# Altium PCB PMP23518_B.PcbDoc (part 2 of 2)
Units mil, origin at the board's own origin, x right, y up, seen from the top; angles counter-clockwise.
Board outline 2200 x 2200 mil, 2 copper layers (Top Layer, Bottom Layer), stack 62 mil thick; 74 components, 34 nets, 163 pads, 51 vias.
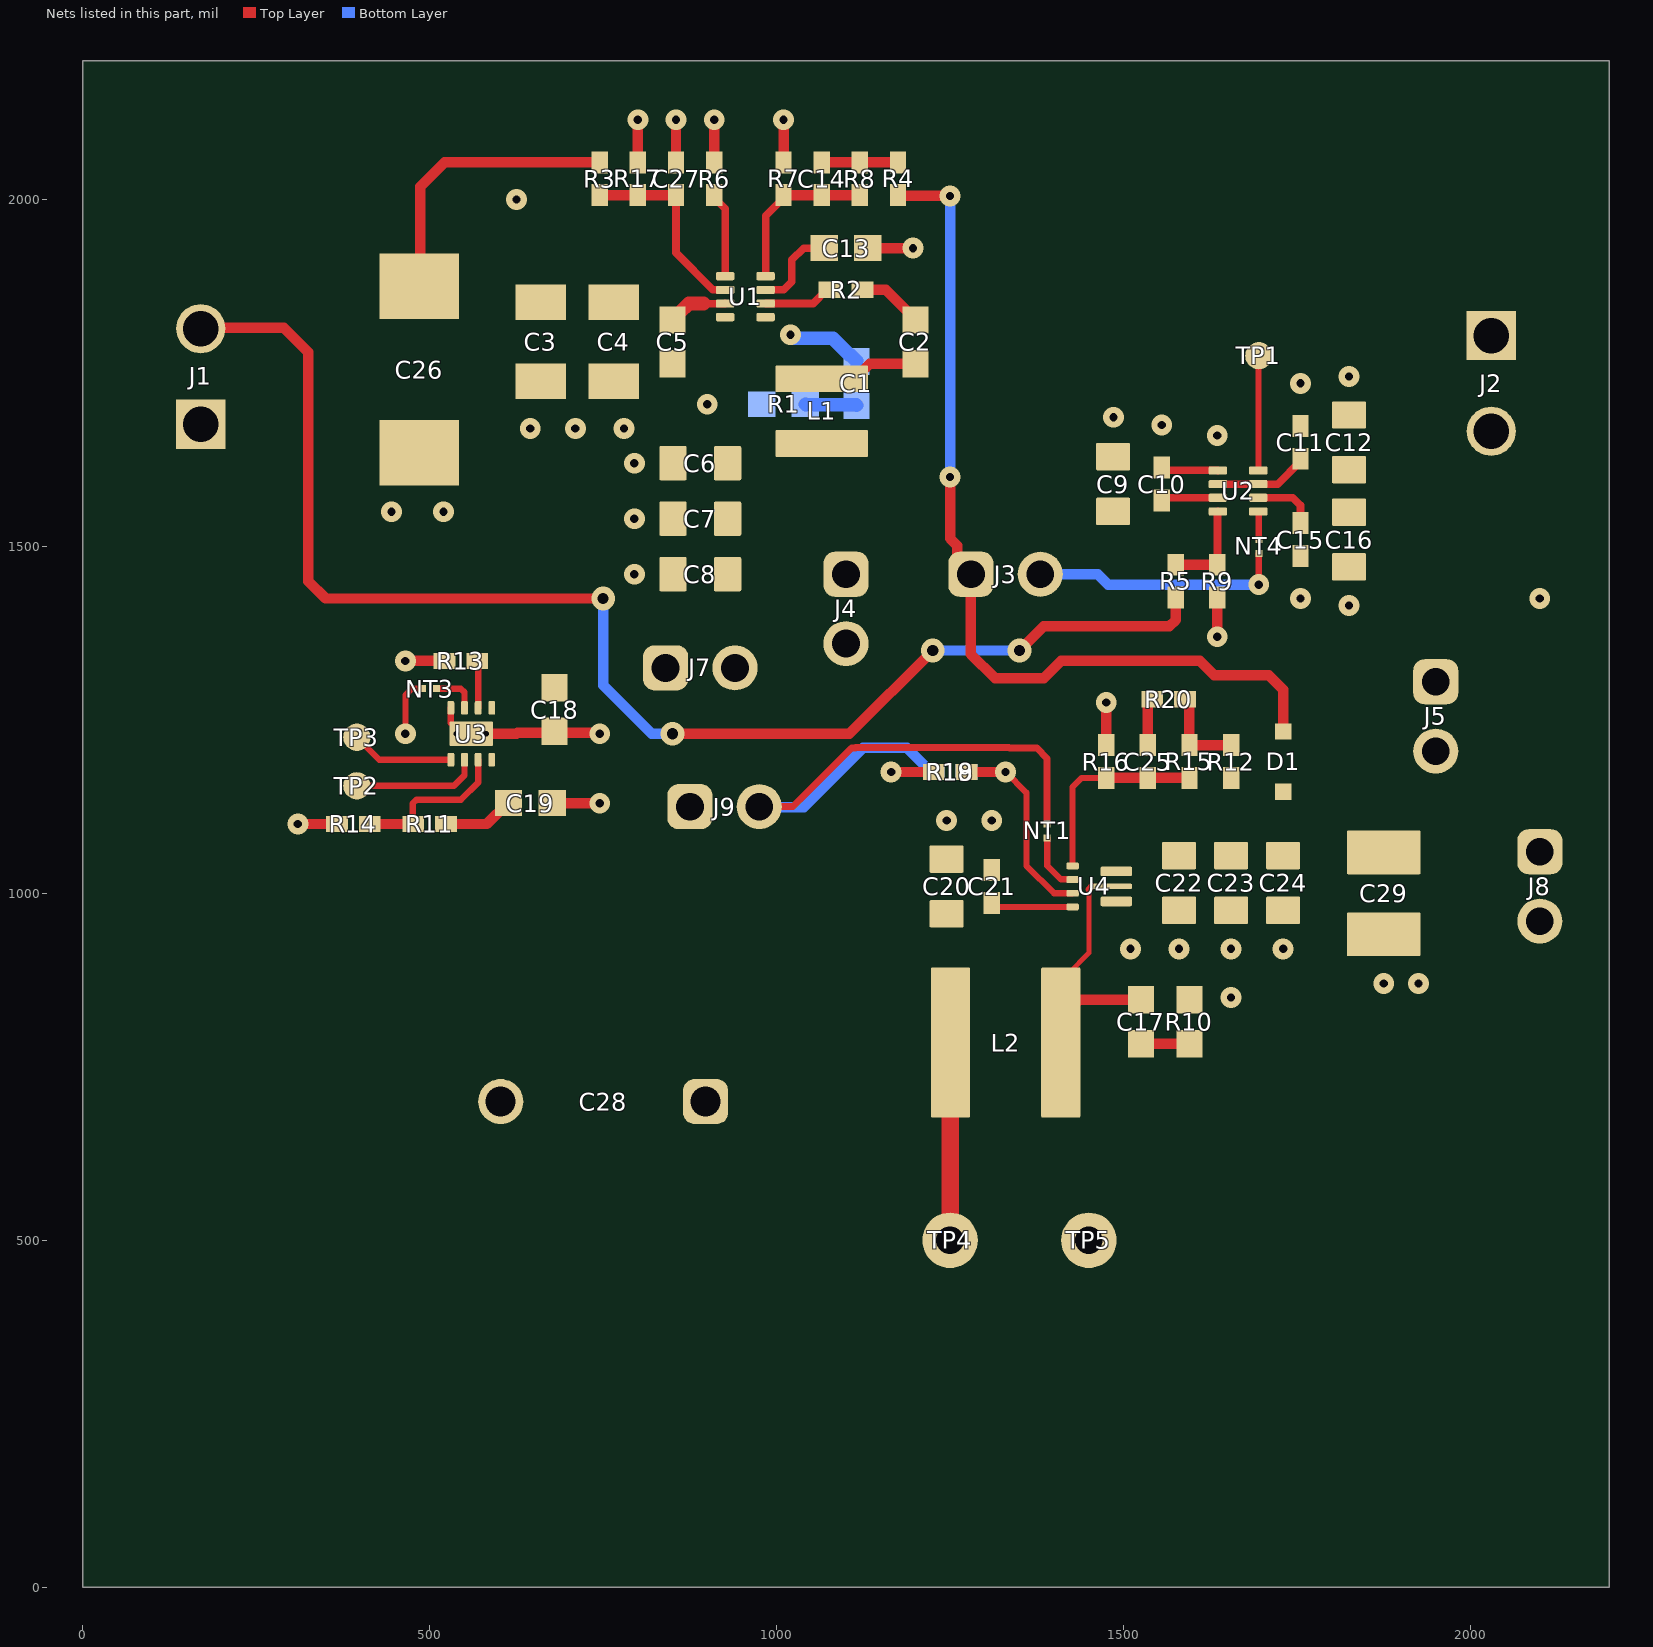
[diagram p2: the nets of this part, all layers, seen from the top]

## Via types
v1: diameter 30, hole 12, Top Layer to Bottom Layer, 45 vias
v2: diameter 34, hole 16, Top Layer to Bottom Layer, 4 vias
v3: diameter 19.68, hole 7.87, Top Layer to Bottom Layer, 2 vias

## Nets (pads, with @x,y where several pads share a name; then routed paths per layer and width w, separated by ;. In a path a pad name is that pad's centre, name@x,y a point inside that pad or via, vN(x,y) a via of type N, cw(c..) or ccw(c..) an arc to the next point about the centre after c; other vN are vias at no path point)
GND: C3.1 C4.1 C5.1 C6.1 C7.1 C8.1 C9.1 C10.2 C11.2 C12.1 C13.1 C15.2 C16.2 C18.1 C19.1 C20.1 C21.2 C22.1 C23.1 C24.1 C26.2 C27.1 C28.2 C29.2 J1.1 J2.1 J4.2 J8.2 NT3.1 R1.2 R6.2 R7.2 R9.2 R10.2 R13.2 R14.2 R16.2 R17.2 R19.1 TP5.1 U1.4 U2.1 U3.4 U3.9 U4.1 | length 1045.1
  Top Layer w9: v1(465,1230) 465,1285.69 474.31,1295 NT3.1@490,1295 ; U3.4@530.47,1267.4 530.47,1245.75 538.35,1237.87 v3(538.35,1230)
  Top Layer w11: C10.2@1555,1613.62 1558.69,1609.93 1635.46,1609.93 U2.1@1635.87,1609.53
  Top Layer w15: v1(310,1100) R14.2@366.38,1100 ; v1(465,1335) R13.2@521.38,1335 ; v3(581.65,1230) 625,1230 626.75,1231.75 678.25,1231.75 C18.1@680,1233.5 681.75,1231.75 743.25,1231.75 v1(745,1230) ; C19.1@676.5,1130 v1(745,1130) ; R17.2@800,2053.62 v1(800,2115) ; C27.1@855,2053.62 v1(855,2115) ; R6.2@910,2053.62 v1(910,2115) ; R7.2@1010,2053.62 v1(1010,2115) ; C13.1@1131.5,1930 v1(1196.65,1930) ; v1(1165,1175) R19.1@1226.38,1175 ; R16.2@1475,1213.62 v1(1475,1275) ; v1(1635,1370) R9.2@1635,1426.38
  other v1: 1655,850 1875,870 1925,870 1510,920 1580,920 1655,920 1730,920 1245,1105 1310,1105 1825,1415 1755,1425 2100,1425 795,1460 795,1540 445,1550 520,1550 795,1620 1635,1660 645,1670 710,1670 780,1670 1555,1675 1485.52,1686.3 900,1705 1755,1735 1825,1745 625,2000
NetC1_1: C1.1 R1.1 | length 74.1
  Bottom Layer w20: R1.1@1041.5,1705 1042.24,1704.25 1114.25,1704.25 C1.1@1115,1703.5
NetC1_2: C1.2 C2.2 L1.1 U1.5 | length 248.5
  Top Layer w15: L1.1@1065,1741.65 1112.64,1741.65 1134.49,1763.5 C2.2@1200,1763.5
  Bottom Layer w20: v1@1025,1800 1081.5,1800 1105.31,1776.18 1106.3,1776.18 1115,1767.48 C1.2@1115,1766.5
  other v1: 1020,1805
NetC2_1: C2.1 R2.2 | length 95
  Top Layer w15: R2.2@1123.62,1870 1157.48,1870 1200,1827.48 C2.1@1200,1826.5
NetC9_2: C9.2 C10.1 J3.2 NT4.2 U2.3 | length 448.6
  Top Layer w9: v1(1695,1445) NT4.2@1695,1490
  Top Layer w11: C10.1@1555,1566.38 1558.78,1570.16 U2.3@1635.87,1570.16
  Bottom Layer w15: J3.2@1380,1460 1462.87,1460 1477.87,1445 v1(1695,1445)
NetC11_1: C11.1 C12.2 J2.2 U2.2 U2.7 | length 136.6
  Top Layer w11: U2.2@1635.87,1589.84 U2.7@1694.13,1589.84 1722.4,1589.84 1755,1622.44 C11.1@1755,1626.38
NetC13_2: C13.2 U1.7 | length 127.6
  Top Layer w11: U1.7@984.13,1869.84 1010.03,1869.84 1022,1881.81 1022,1913.02 1038.98,1930 C13.2@1068.5,1930
NetC14_1: C14.1 R4.1 R8.1 | length 110
  Top Layer w15: C14.1@1065,2053.62 R8.1@1120,2053.62 R4.1@1175,2053.62
NetC14_2: C14.2 R7.1 R8.2 U1.8 | length 237.6
  Top Layer w11: U1.8@984.13,1889.53 984.13,1976.57 1010,2002.44 R7.1@1010,2006.38
  Top Layer w15: R7.1@1010,2006.38 C14.2@1065,2006.38 R8.2@1120,2006.38
NetC15_1: C15.1 C16.1 J5.1 U2.6 | length 91
  Top Layer w11: U2.6@1694.13,1570.16 1744.06,1570.16 1755,1559.21 C15.1@1755,1533.62
NetC17_1: C17.1 R10.1 | length 70
  Top Layer w15: C17.1@1525,783.5 R10.1@1595,783.5
NetC17_2: C17.2 L2.2 U4.2 | length 350
  Top Layer w7: L2.2@1420.16,830.77 1420.16,884.29 1450,914.13 1450,1005.9 ; 1454.1,1010 U4.2@1483.7,1010
  Top Layer w10: 1450,1005.9 1454.1,1010
  Top Layer w15: L2.2@1420.16,815 1420.16,830.77 1435.89,846.5 C17.2@1525,846.5
NetC18_2: C18.2 J7.1 U3.1
NetC19_2: C19.2 J9.1 R11.1 U3.8 | length 102.3
  Top Layer w15: R11.1@523.62,1100 582.52,1100 612.52,1130 C19.2@613.5,1130
NetC20_2: C20.2 C21.1 C28.1 J9.2 L2.1 NT1.1 R18.1 TP4.1 U4.7 | length 1257.2
  Top Layer w9: C21.1@1310,986.38 1315.91,980.47 U4.7@1426.61,980.47
  Top Layer w10: J9.2@975,1125 1023.62,1125 1108.25,1209.63 1113.44,1209.63 1113.81,1210 1335,1210 1335.37,1209.63 1375,1209.63 1390,1194.63 NT1.1@1390,1100
  Top Layer w25: TP4.1@1250,500 1250.24,500.24 1250.24,784.76 L2.1@1250.47,785
  Bottom Layer w15: J9.2@975,1125 975.76,1124.24 1038.98,1124.24 1124.73,1210 1187.44,1210 1222.44,1175 R18.1@1226.38,1175
NetC22_2: C22.2 C23.2 C24.2 C29.1 D1.1 J5.2 J8.1 R12.2 U4.3
NetC25_1: C25.1 R20.1 | length 70.2
  Top Layer w15: C25.1@1535,1213.62 1535,1275.69 1539.31,1280 R20.1@1541.38,1280
NetC25_2: C25.2 R15.2 R16.1 U4.4 | length 287.6
  Top Layer w9: U4.4@1426.61,1039.53 1426.61,1153.42 1439.58,1166.38 R16.1@1475,1166.38
  Top Layer w15: R16.1@1475,1166.38 C25.2@1535,1166.38 R15.2@1595,1166.38
NetC27_2: C27.2 R3.2 R17.1 U1.2 | length 286
  Top Layer w11: C27.2@855,2006.38 855,1923.53 908.28,1870.25 925.46,1870.25 U1.2@925.87,1869.84
  Top Layer w15: R3.2@745,2006.38 R17.1@800,2006.38 C27.2@855,2006.38
NetNT1_2: NT1.2 U4.5 | length 85
  Top Layer w9: NT1.2@1390,1080 1390,1040 1409.74,1020.26 1426.19,1020.26 U4.5@1426.61,1019.84
NetNT3_2: NT3.2 U3.3 | length 64.7
  Top Layer w9: NT3.2@510,1295 544.89,1295 550.16,1289.73 U3.3@550.16,1267.4
NetNT4_1: NT4.1 U2.5 | length 40.8
  Top Layer w9: U2.5@1694.13,1550.47 1695,1549.61 NT4.1@1695,1510
NetR2_1: R2.1 U1.6 | length 100.5
  Top Layer w11: U1.6@984.13,1850.16 1052.6,1850.16 1072.44,1870 R2.1@1076.38,1870
NetR5_2: R5.2 R9.1 U2.4 | length 137.2
  Top Layer w11: R9.1@1635,1473.62 1635.43,1474.05 1635.43,1550.07 U2.4@1635.84,1550.47
  Top Layer w15: R5.2@1575,1473.62 R9.1@1635,1473.62
NetR6_1: R6.1 U1.1 | length 123.4
  Top Layer w11: R6.1@910,2006.38 910,2002.44 925.87,1986.57 U1.1@925.87,1889.53
NetR11_2: R11.2 R14.1 U3.7 | length 230.8
  Top Layer w9: R11.2@475.69,1100.69 475.69,1129.73 480.96,1135 545,1135 569.84,1159.84 U3.7@569.84,1192.6
  Top Layer w15: R14.1@413.62,1100 475,1100 R11.2@475.69,1100.69
NetR12_1: R12.1 R15.1 R20.2 | length 130.2
  Top Layer w15: R20.2@1588.62,1280 1590.69,1280 1595,1275.69 R15.1@1595,1213.62 R12.1@1655,1213.62
NetR13_1: R13.1 U3.2 | length 68.1
  Top Layer w9: R13.1@568.62,1335 569.84,1333.78 U3.2@569.84,1267.4
NetR18_2: R18.2 R19.2 U4.6 | length 343.3
  Top Layer w9: v1(1330,1175) 1360,1145 1360,1040 1399.84,1000.16 U4.6@1426.61,1000.16
  Top Layer w15: R19.2@1273.62,1175 v1(1330,1175)
  Bottom Layer w15: R18.2@1273.62,1175 v1(1330,1175)
NetTP1_1: TP1.1 U2.8 | length 165.8
  Top Layer w9: U2.8@1694.13,1609.53 1694.57,1609.96 1694.57,1774.57 TP1.1@1695,1775
NetTP2_1: TP2.1 U3.6 | length 183.9
  Top Layer w9: TP2.1@395,1155 535,1155 550.16,1170.16 U3.6@550.16,1192.6
NetTP3_1: TP3.1 U3.5 | length 148.9
  Top Layer w9: TP3.1@395,1225 427.4,1192.6 U3.5@530.47,1192.6
VBUCK: C6.2 C7.2 C8.2 D1.2 J3.1 J4.1 J7.2 L1.2 R4.2 | length 1300.3
  Top Layer w15: R4.2@1175,2006.38 1175.69,2005.69 1249.31,2005.69 v1(1250,2005) ; v1(1250,1600) 1250,1511.46 1260.42,1501.04 1260.42,1479.58 J3.1@1280,1460 1280,1345 1315,1310 1385,1310 1410,1335 1610,1335 1630.58,1314.42 1709.13,1314.42 1730,1293.55 D1.2@1730,1233.31
  Bottom Layer w15: v1(1250,1600) v1(1250,2005)
VIN: C3.2 C4.2 C5.2 C26.1 J1.2 R3.1 R5.1 U1.3 | length 2517.5
  Top Layer w11: 895,1850 925.71,1850 U1.3@925.87,1850.16
  Top Layer w15: J1.2@170,1815 290,1815 325,1780 325,1450 350,1425 v2(750,1425) ; C26.1@485,1875.08 486.22,1876.3 486.22,2018.19 521.65,2053.62 R3.1@745,2053.62 ; v2(850,1230) 1105,1230 v2(1225,1350) ; v2(1350,1350) 1385.2,1385.2 1566.21,1385.2 1575,1393.98 R5.1@1575,1426.38
  Top Layer w20: C5.2@850,1826.5 850,1827.48 858.7,1836.18 859.69,1836.18 873.5,1850 895,1850
  Bottom Layer w15: v2(750,1425) 750,1300 820,1230 v2(850,1230) ; v2(1225,1350) v2(1350,1350)

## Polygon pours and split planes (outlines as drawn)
GND on Top Layer "TOP_LAYER_GND_P011" (solid, remove dead copper, pour order 11): 50,2150 50,50 2150,50 2150,2150
NetC18_2 on Top Layer "TOP_LAYER_NETC18_2_P010" (solid, remove dead copper, pour order 10): 895,1275 655,1275 640,1260 585,1260 585,1280 685,1375 895,1375
NetC19_2 on Top Layer "TOP_LAYER_NETC19_2_P009" (solid, remove dead copper, pour order 9): 555,950 910,950 910,1175 800,1175 800,1050 635,1050 635,1200 585,1200 585,1160 555,1130
NetC22_2 on Top Layer "TOP_LAYER_NETC22_2_P008" (solid, remove dead copper, pour order 8): 2150,1025 2150,1240 1800,1240 1800,1180 1640,1180 1640,1100 1465,1100 1465,1025
NetC20_2 on Top Layer "TOP_LAYER_NETC20_2_P007" (solid, remove dead copper, pour order 7): 800,900 940,900 940,1175 1075,1175 1075,1000 1190,1000 1370,1000 1385,985 1400,985 1400,970 1350,970 1350,600 800,600
NetC17_2 on Top Layer "TOP_LAYER_NETC17_2_P006" (solid, remove dead copper, pour order 6): 1445,965 1430,950 1375,950 1375,650 1455,650 1455,1015 1445,1015
NetC11_1 on Top Layer "TOP_LAYER_NETC11_1_P005" (solid, remove dead copper, pour order 5): 1730,1590 2150,1590 2150,1730 1900,1730 1900,1640 1730,1640
NetC15_1 on Top Layer "TOP_LAYER_NETC15_1_P004" (solid, remove dead copper, pour order 4): 1900,1265 1900,1520 1730,1520 1730,1575 2000,1575 2000,1265
NetC9_2 on Top Layer "TOP_LAYER_NETC9_2_P003" (solid, remove dead copper, pour order 3): 1340,1420 1340,1580 1605,1580 1605,1540 1525,1540 1525,1420
VBUCK on Top Layer "TOP_LAYER_VBUCK_P002" (solid, remove dead copper, pour order 2): 905,1275 1000,1275 1000,1420 1315,1420 1315,1550 1160,1550 1160,1680 905,1680
NetC1_2 on Top Layer "TOP_LAYER_NETC1_2_P001" (solid, remove dead copper, pour order 1): 975,1835 975,1700 1160,1700 1160,1800 1050,1800 1015,1835
VIN on Top Layer "TOP_LAYER_VIN_P000" (solid, remove dead copper, pour order 0): 50,1760 550,1760 595,1805 885,1805 885,1860 845,1860 755,1950 50,1950
GND on Bottom Layer "BOTTOM_LAYER_GND_P012" (solid, remove dead copper, pour order 12): 50,2150 2150,2150 2150,50 50,50

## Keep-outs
Keep-Out Layer:
  text ".Layer_Name" at 577,-858.49 h60

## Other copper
Top Layer:
  text ".Layer_Name" at 577,-858.49 h60
Bottom Layer:
  text ".Layer_Name" at 577,-858.49 h60

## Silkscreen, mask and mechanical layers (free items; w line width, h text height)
Top Overlay:
  text "GND" at 1981,1936 h40
  text "VIN" at 71,1919.02 h40
  text "GND" at 71,1516 h40
  text "VOUT" at 1961,1504.19 h40
  text "'.PRJ_Number'.PCB_Rev" at 1565.5,230 h108.27
  text ".Layer_Name" at 577,-858.49 h60
Bottom Overlay:
  text ".Layer_Name" at 577,-858.49 h60
Top Paste:
  text ".Layer_Name" at 577,-858.49 h60
Bottom Paste:
  text ".Layer_Name" at 577,-858.49 h60
Top Solder:
  text ".Layer_Name" at 577,-858.49 h60
  text ".Layer_Name" at 577,-858.49 h60
Bottom Solder:
  text ".Layer_Name" at 577,-858.49 h60
Drill Guide:
  text ".Layer_Name" at 577,-858.49 h60
M1 Board Outline:
  the board outline again, w10
  text ".Layer_Name" at 577,-858.49 h60
M2 Board Dimensions:
  rectangle: 0,-275 125,-150
  rectangle: 125,-400 500,-275
  lines w7: 0,-275 1000,-275 ; 125,-400 125,-150 ; 250,-400 250,-150 ; 500,-400 500,-150 ; 750,-400 750,-150 ; 0,-400 1000,-400 1000,-150 0,-150 0,-400
  text ".Layer_Name" at 577,-858.49 h60
M3 3D STEP Top:
  text ".Layer_Name" at 577,-858.49 h60
M4 3D STEP Bottom:
  text ".Layer_Name" at 577,-858.49 h60
M5 Assembly Top:
  lines w10: -292,-930.17 6308,-930.17 ; -292,-726.83 6310,-726.83 ; -292,-523.5 -292,-1133.5 3713,-1133.5 6310,-1133.5 6310,-523.5 -291.5,-523.5 -291.5,-1133.5 1284,-1133.5 ; 2173,-1133.5 2173,-523.5 ; 3440,-726.83 3440,-523.5 ; 4280,-726.83 4280,-523.5 ; 4902,-1140 4902,-937.17
  text "COMPONENTS MARKED 'DNP' SHOULD NOT BE POPULATED." at 1153.5,-318.5 h60
  text "ASSEMBLY VARIANT:" at 1153,-434 h60
  text ".VariantName" at 2189,-434 h60
  text "PCB VIEWED FROM TOP SIDE" at -228.5,-655.67 h60
  text "BOARD #:" at 2248,-655.67 h60
  text ".PRJ_Number" at 2793.5,-655.67 h60
  text "REV:" at 3638,-655.67 h60
  text ".PCB_Rev" at 3929.5,-655.67 h60
  text "SVN REV:" at 4476,-655.67 h60
  text ".VersionControl_RevNumber" at 4982,-655.67 h60
  text "TID #:" at 2248,-859 h60
  text ".TID" at 2793.5,-859 h60
  text "PLOT NAME =" at -228.5,-1064.34 h60
  text ".plot_File_Name" at 577,-1064.34 h60
  text "GENERATED    :" at 2250,-1064.34 h60
  text ".Print_Date" at 3119.5,-1064.34 h60
  text ".Print_Time" at 3848.5,-1064.34 h60
  text "TEXAS INSTRUMENTS" at 5113,-1064.34 h60
M6 Assembly Bottom:
  lines w10: -292.5,-727.33 6309.5,-727.33 ; -290.5,-930.67 6309.5,-930.67 ; 1115.5,-1140.5 1115.5,-937.67 ; 1737.5,-727.33 1737.5,-524 ; 2577.5,-727.33 2577.5,-524 ; 3844.5,-1134 3844.5,-524 ; 4733.5,-1134 6309,-1134 6309,-524 -292.5,-524 -292.5,-1134 2304.5,-1134 6309.5,-1134 6309.5,-524
  text "COMPONENTS MARKED 'DNP' SHOULD NOT BE POPULATED." at 6102,-318 h60
  text ".VariantName" at 5058,-434 h60
  text "ASSEMBLY VARIANT:" at 6097,-434 h60
  text ".VersionControl_RevNumber" at 1035.5,-656.17 h60
  text "SVN REV:" at 1541.5,-656.17 h60
  text ".PCB_Rev" at 2088,-656.17 h60
  text "REV:" at 2379.5,-656.17 h60
  text ".PRJ_Number" at 3224,-656.17 h60
  text "BOARD #:" at 3769.5,-656.17 h60
  text "PCB VIEWED FROM BOTTOM SIDE" at 6246,-656.17 h60
  text ".TID" at 3224,-859.5 h60
  text "TID #:" at 3769.5,-859.5 h60
  text "TEXAS INSTRUMENTS" at 904.5,-1064.84 h60
  text ".Print_Time" at 2169,-1064.84 h60
  text ".Print_Date" at 2898,-1064.84 h60
  text "GENERATED    :" at 3767.5,-1064.84 h60
  text ".plot_File_Name" at 5440.5,-1064.84 h60
  text "PLOT NAME =" at 6246,-1064.84 h60
M9 Title Sheet:
  drawing of 57 lines, arcs and shapes, not listed
  text "1" at 739.84,8036.5 h70
  text "2" at 3235.5,8036.5 h70
  text "3" at 5724.84,8036.5 h70
  text "4" at 8231.51,8036.5 h70
  text "5" at 10730.5,8036.5 h70
  text "6" at 13235.5,8036.5 h70
  text "A" at -416.5,6893.5 h70
  text "A" at 14383.5,6893.5 h70
  text "B" at -416.5,4513.5 h70
  text "B" at 14383.5,4513.5 h70
  text "C" at -416.5,2138.5 h70
  text "C" at 14383.5,2138.5 h70
  text "PROJECT TITLE:" at 11343.5,277.5 h45
  text ".PRJ_Title" at 11393.5,144.17 h70
  text "DESIGNED FOR:" at 11343.5,-23.5 h45
  text ".PRJ_Customer" at 11393.5,-163.5 h70
  text "D" at -416.5,-231.5 h70
  text "D" at 14383.5,-231.5 h70
  text "FILE NAME:" at 11343.5,-323.5 h45
  text ".PCB_File_Name_No_Path" at 11393.5,-443.5 h70
  text "Texas Instruments (TI) and/or its licensors do not warrant the accuracy or completeness of this specification" at 6374,-605.34 h45
  text "ENGINEER:" at 11343.5,-613.5 h45
  text "LAYOUT BY:" at 12848.5,-613.5 h45
  text "or any information contained therein. TI and/or its licensors do not warrant that this design will meet" at 6329.01,-718 h45
  text ".PRJ_Engineer" at 11393.5,-768.49 h70
  text ".PCB_Layout" at 12899,-768.49 h70
  text "the specifications, will be suitable for your application or fit for any particular purpose, or will operate in" at 6329.01,-830.67 h45
  text ".Layer_Name" at 577,-858.49 h60
  text "ALTIUM DESIGNER VERSION:" at 12848.5,-923.5 h45
  text "an implementation. TI and/or its licensors do not warrant that the design is production worthy. You should" at 6329.01,-943.33 h45
  text "completely validate and test your design implementation to confirm the system functionality for your application." at 6374,-1056 h45
  text ".print_Scale" at 11393.5,-1056.83 h70
  text ".Application_BuildNumber" at 12899,-1056.83 h70
  text "1" at 739.84,-1263.5 h70
  text "2" at 3235.5,-1263.5 h70
  text "3" at 5724.84,-1263.5 h70
  text "4" at 8231.51,-1263.5 h70
  text "5" at 10730.5,-1263.5 h70
  text "6" at 13235.5,-1263.5 h70
M10 Fab Notes:
  drawing of 189 lines, arcs and shapes, not listed
  text "DESIGN INFORMATION" at 12382.02,6356.17 h60
  text "MIN. TRACK WIDTH:" at 11737.46,6224.05 h60
  text "8" at 12833.7,6224.05 h60
  text "MIL" at 12988.46,6224.05 h60
  text "7.874" at 12667.32,6102.36 h60
  text "MIN. CLEARANCE:" at 11737.46,6099.92 h60
  text "MIL" at 12988.46,6099.92 h60
  text "MIN. VIA PAD SIZE:" at 11737.46,5975.8 h60
  text "24" at 12803.71,5975.8 h60
  text "MIL" at 12988.46,5975.8 h60
  text "0.05mm (2MIL)" at 12432.46,5845.9 h60
  text "MINIMUM ANNULAR RING" at 11408.23,5837.67 h60
  text "EXTERNAL" at 13140.46,5837.67 h60
  text "PER" at 11608.23,5727.55 h60
  text "IPC-D-275 CLASS 2 LEVEL C" at 11828.23,5727.54 h60
  text "MIL, HOLES" at 13316.46,5627.07 h60
  text "+/-" at 12924,5618.48 h60
  text "+/-" at 13778,5618.48 h60
  text "REGISTRATION TOLERANCES:" at 11408.23,5617.42 h60
  text "METAL" at 12608,5617.42 h60
  text "5" at 13184.2,5617.42 h60
  text "3" at 14017.2,5617.42 h60
  text "MIL" at 14133.46,5617.42 h60
  text "HOLE SIZE TOLERANCE (UNLESS OTHERWISE SPECIFIED):" at 11408.23,5519.1 h60
  text "+/-" at 13778,5516.23 h60
  text "3" at 14017.2,5515.17 h60
  text "MIL" at 14133.46,5515.17 h60
  text "MATERIAL:" at 11333.46,5377.52 h60
  text "FR-4 High Tg" at 12319.9,5249 h60
  text "X" at 12175.46,5241.01 h60
  text "FR-4" at 11754.46,5236.49 h60
  text "OTHER" at 13242.46,5236.49 h60
  text "62 MIL (1.6mm) +/-10%" at 12074.56,5093.46 h60
  text "X" at 11954.46,5091.01 h60
  text "THICKNESS:" at 11408.23,5085.24 h60
  text "OTHER" at 13359.46,5085.24 h60
  text "TOLERANCE:" at 11408.23,4946.92 h60
  text "X" at 12256.46,4946.92 h60
  text "ANSI IPC-6012 TYPE 3 CLASS 2" at 12434.48,4946.92 h60
  text "OTHER +/-" at 12434.46,4802.73 h60
  text "BOW & TWIST:" at 11408.23,4657.54 h60
  text "X" at 12256.46,4657.54 h60
  text "ANSI IPC-6012 TYPE 3 CLASS 2" at 12434.48,4657.54 h60
  text "OTHER +/-" at 12434.46,4510.85 h60
  text "DRILLING:" at 11333.46,4380.23 h60
  text "NC_DRILL FILES" at 13094.46,4275.04 h60
  text "REFERENCE:" at 11408.23,4271.1 h60
  text "X" at 12065.46,4271.01 h60
  text "AS SHOWN" at 12243.46,4271.1 h60
  text "X" at 12966.46,4271.1 h60
  text "OTHER" at 13392.46,4128.85 h60
  text "PTH COPPER THICKNESS:" at 11407.91,4125.32 h60
  text "X" at 12547.14,4125.32 h60
  text "20-30 um" at 12675.14,4125.32 h60
  text "BOARD FINISH:" at 11333.46,3977.73 h60
  text "SILKSCREEN:" at 11488.68,3867.6 h60
  text "X" at 12446.46,3867.6 h60
  text "TOP" at 12563.46,3867.6 h60
  text "X" at 12956.46,3867.6 h60
  text "BOTTOM" at 13074.46,3867.6 h60
  text "SILKSCREEN COLOR:" at 11488.68,3712.41 h60
  text "X" at 12445.46,3712.41 h60
  text "WHITE" at 12563.46,3712.41 h60
  text "OTHER" at 13074.46,3712.41 h60
  text "X" at 12576.46,3568.96 h60
  text "GREEN" at 12694.46,3568.96 h60
  text "OTHER" at 13312.46,3568.96 h60
  text "SOLDER RESIST COLOR:" at 11488.68,3562.1 h60
  text "X" at 12576.46,3414.71 h60
  text "MATTE" at 12694.46,3414.71 h60
  text "SEMI-GLOSS" at 13312,3414.07 h60
  text "IMMERSION GOLD (ENIG)" at 12394.46,3241.94 h60
  text "ENEPIG" at 13732,3234.72 h60
  text "SURFACE FINISH:" at 11333.46,3233.72 h60
  text "X" at 12216.46,3233.72 h60
  text "IMM. TIN/SILVER OR EQUIV" at 11663,3096.4 h60
  text "OTHER" at 13094.46,3092.47 h60
  text "ARRAY/PANEL:" at 11333.46,2937.09 h60
  text "CUT AND TRIM PER M1 BOARD OUTLINE" at 12394.46,2928.87 h60
  text "N.C. ROUTE" at 12394.46,2792.9 h60
  text "X" at 13082.46,2792.9 h60
  text "V. SCORE" at 13260.46,2792.9 h60
  text "CERTIFICATION:" at 11333.46,2663.77 h60
  text "MATERIALS AND WORKMANSHIP FOR ALL PCBS" at 12058.46,2663.77 h60
  text "TO MEET OR EXCEED THE REQUIREMENTS OF:" at 12058.46,2569.71 h60
  text "X" at 11695.97,2441.08 h60
  text "ANSI IPC-A-600F CLASS ->" at 11823.96,2441.08 h60
  text "X" at 13471.97,2441.08 h60
  text "2" at 13581.96,2441.08 h60
  text "1" at 13266.96,2439.58 h60
  text "3" at 13935.96,2439.58 h60
  text "X" at 12507.97,2293.39 h60
  text "RoHS" at 12635.96,2293.39 h60
  text "OTHER" at 13280.36,2293.39 h60
  text "PER ORDER" at 13677.42,2293.39 h60
  text "ALL BOARDS MUST MEET OR EXCEED UL94-V0 REQUIREMENTS." at 11361,2139.57 h60
  text "PCB MUST BEAR THE UL94V-0 UL REGISTERED MATERIAL ID NUMBER" at 11361,2023.5 h60
  text "ADDITIONAL REQUIREMENTS:" at 11333.46,1854.08 h60
  text "MICROSECTION:" at 11408.23,1746.95 h60
  text "YES" at 12313.96,1746.95 h60
  text "REQUIRED" at 13175.46,1602.62 h60
  text "BARE BOARD ELEC. TEST:" at 11408.23,1599.76 h60
  text "NONE" at 12713.96,1599.76 h60
  text "X" at 13057.46,1599.76 h60
  text "PER ORDER" at 13767.46,1599.76 h60
  text "XX MIL VIAS REQUIRE NON-CONDUCTIVE FILL AND PLANARIZE" at 11576.38,1394.82 h59
  text "XX MIL VIAS REQUIRE CONDUCTIVE FILL AND PLANARIZE" at 11584.38,1290.84 h60
  text "OUTER XX MIL TRACES REQUIRE 50 OHM SINGLE-ENDED IMPEDANCE" at 11583.39,1127.46 h58
  text "LAYER 2 & 3 (INNER LAYERS) XX MIL WIDE, XX MIL SPACE / TRACES REQUIRE 100 OHM DIFFERENTIAL IMPEDANCE" at 11575.39,891.74 h60
  text ".Layer_Name" at 577,-858.49 h60
M11 Gerber Information:
  lines w10: -292,-930.17 6308,-930.17 ; -292,-726.83 6310,-726.83 ; -292,-523.5 -292,-1133.5 3713,-1133.5 6310,-1133.5 6310,-523.5 -291.5,-523.5 -291.5,-1133.5 1284,-1133.5 ; 2173,-1133.5 2173,-523.5 ; 3440,-726.83 3440,-523.5 ; 4280,-726.83 4280,-523.5 ; 4902,-1140 4902,-937.17
  text "ALL ARTWORK VIEWED FROM TOP SIDE" at -228.5,-655.67 h60
  text "BOARD #:" at 2248,-655.67 h60
  text ".PRJ_Number" at 2793.5,-655.67 h60
  text "REV:" at 3638,-655.67 h60
  text ".PCB_Rev" at 3929.5,-655.67 h60
  text "SVN REV:" at 4476,-655.67 h60
  text ".VersionControl_RevNumber" at 4982,-655.67 h60
  text "LAYER NAME =" at -228.5,-858.49 h60
  text "TID #:" at 2248,-859 h60
  text ".TID" at 2793.5,-859 h60
  text "PLOT NAME =" at -228.5,-1064.34 h60
  text ".plot_File_Name" at 577,-1064.34 h60
  text "GENERATED    :" at 2250,-1064.34 h60
  text ".Print_Date" at 3119.5,-1064.34 h60
  text ".Print_Time" at 3848.5,-1064.34 h60
  text "TEXAS INSTRUMENTS" at 5113,-1064.34 h60
M12 Stackup:
  drawing of 191 lines, arcs and shapes, not listed
  text "Layer" at 9821.59,7874.94 h60
  text "Name" at 10231.51,7874.94 h60
  text "Material" at 11161.25,7874.94 h60
  text "Thickness" at 12021.02,7874.94 h60
  text "Constant" at 12670.85,7874.94 h60
  text "Board Layer Stack" at 13240.71,7874.94 h60
  text "Top Overlay" at 10231.51,7754.94 h60
  text "Top Solder" at 10231.51,7634.94 h60
  text "Solder Resist" at 11161.25,7634.94 h60
  text "0.40mil" at 12021.02,7634.94 h60
  text "3.5" at 12670.85,7634.94 h60
  text "1" at 9821.59,7514.94 h60
  text "Top Layer" at 10231.51,7514.94 h60
  text "1.40mil" at 12021.02,7514.94 h60
  text "Dielectric1" at 10231.51,7394.94 h60
  text "FR-4 High Tg" at 11161.25,7394.94 h60
  text "59.20mil" at 12021.02,7394.94 h60
  text "4.8" at 12670.85,7394.94 h60
  text "2" at 9821.59,7274.94 h60
  text "Bottom Layer" at 10231.51,7274.94 h60
  text "1.40mil" at 12021.02,7274.94 h60
  text "Bottom Solder" at 10231.51,7154.94 h60
  text "Solder Resist" at 11161.25,7154.94 h60
  text "0.40mil" at 12021.02,7154.94 h60
  text "3.5" at 12670.85,7154.94 h60
  text "Bottom Overlay" at 10231.51,7034.94 h60
  text ".Layer_Name" at 577,-858.49 h60
M13 Component Bodies Top:
  text ".Layer_Name" at 577,-858.49 h60
M14 Component Bodies Bottom:
  text ".Layer_Name" at 577,-858.49 h60
M15 Courtyards Top:
  text ".Layer_Name" at 577,-858.49 h60
M16 Courtyards Bottom:
  text ".Layer_Name" at 577,-858.49 h60
Drill Drawing:
  lines w10: 2630.98,167.23 2630.98,181.02 2644.76,194.8 2630.98,208.58 2630.98,222.36 2644.76,222.36 2658.54,208.58 2672.32,222.36 2686.1,222.36 2686.1,208.58 2672.32,194.8 2686.1,181.02 2686.1,167.23 2672.32,167.23 2658.54,181.02 2644.76,167.23 2630.98,167.23 ; 2630.98,346.38 2686.1,346.38 2658.54,291.26 2630.98,346.38 ; 2630.98,415.29 2686.1,415.29 2686.1,470.41 2630.98,470.41 2630.98,415.29 ; 2630.98,553.1 2644.76,553.1 2644.76,539.31 2672.32,539.31 2672.32,553.1 2686.1,553.1 2686.1,580.66 2672.32,580.66 2672.32,594.44 2644.76,594.44 2644.76,580.66 2630.98,580.66 2630.98,553.1 ; 2630.98,663.34 2658.54,677.12 2686.1,663.34 2672.32,690.9 2686.1,718.46 2658.54,704.68 2630.98,718.46 2644.76,690.9 2630.98,663.34 ; 2630.98,801.15 2644.76,801.15 2658.54,787.37 2672.32,801.15 2686.1,801.15 2672.32,814.93 2686.1,828.71 2672.32,828.71 2658.54,842.49 2644.76,828.71 2630.98,828.71 2644.76,814.93 2630.98,801.15
  lines w12: 2581,130.03 5672.83,130.03 ; 2581,874.19 5672.83,874.19 ; 2918.36,6 2918.36,998.21 ; 3189.17,6 3189.17,998.21 ; 3750.94,6 3750.94,998.21 ; 4009.74,6 4009.74,998.21 ; 4384.49,6 4384.49,998.21 ; 5107.03,6 5107.03,998.21 ; 2581,6 5672.83,6 5672.83,998.21 2581,998.21 2581,6
  text "Symbol" at 2655.42,911.39 h72
  text "Count" at 2955.57,911.39 h72
  text "Hole Size" at 3226.38,911.39 h72
  text "Plated" at 3788.15,911.39 h72
  text "Hole Type" at 4046.95,911.39 h72
  text "Drill Layer Pair" at 4421.7,911.39 h72
  text "Hole Tolerance" at 5144.24,911.39 h72
  text "2" at 2955.57,787.37 h60
  text "7.87mil (0.200mm)" at 3226.38,787.37 h60
  text "PTH" at 3788.15,787.37 h60
  text "Round" at 4046.95,787.37 h60
  text "Top Layer - Bottom Layer" at 4421.7,787.37 h60
  text "45" at 2955.57,663.34 h60
  text "12.00mil (0.305mm)" at 3226.38,663.34 h60
  text "PTH" at 3788.15,663.34 h60
  text "Round" at 4046.95,663.34 h60
  text "Top Layer - Bottom Layer" at 4421.7,663.34 h60
  text "4" at 2955.57,539.31 h60
  text "16.00mil (0.406mm)" at 3226.38,539.31 h60
  text "PTH" at 3788.15,539.31 h60
  text "Round" at 4046.95,539.31 h60
  text "Top Layer - Bottom Layer" at 4421.7,539.31 h60
  text "14" at 2955.57,415.29 h60
  text "40.00mil (1.016mm)" at 3226.38,415.29 h60
  text "PTH" at 3788.15,415.29 h60
  text "Round" at 4046.95,415.29 h60
  text "Top Layer - Bottom Layer" at 4421.7,415.29 h60
  text "2" at 2955.57,291.26 h60
  text "43.31mil (1.100mm)" at 3226.38,291.26 h60
  text "PTH" at 3788.15,291.26 h60
  text "Round" at 4046.95,291.26 h60
  text "Top Layer - Bottom Layer" at 4421.7,291.26 h60
  text "4" at 2955.57,167.23 h60
  text "51.18mil (1.300mm)" at 3226.38,167.23 h60
  text "PTH" at 3788.15,167.23 h60
  text "Round" at 4046.95,167.23 h60
  text "Top Layer - Bottom Layer" at 4421.7,167.23 h60
  text "71 Total" at 2955.57,43.21 h60
  text ".Layer_Name" at 577,-858.49 h60
M17 Embedded Cavity:
  text ".Layer_Name" at 577,-858.49 h60
M18 Embedded Assembly:
  text ".Layer_Name" at 577,-858.49 h60
M19 Embedded Keepout:
  text ".Layer_Name" at 577,-858.49 h60

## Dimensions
0,0 to 0,2200 on M2 Board Dimensions
0,0 to 2200,0 on M2 Board Dimensions
0,-400 to 1000,-400 on M2 Board Dimensions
